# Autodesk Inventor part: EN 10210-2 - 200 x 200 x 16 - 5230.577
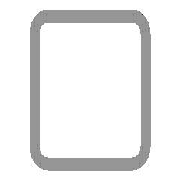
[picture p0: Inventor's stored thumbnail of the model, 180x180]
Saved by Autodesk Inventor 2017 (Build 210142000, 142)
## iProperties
IsCustomPart: 1
Created: 2016-02
Part Number: EN 10210-2 - 200 x 200 x 16 - 5230.577
Material: Steel, Mild
Description: Tube
Document SubType Name: Modeling
Standard: DIN
Designer: iusti
Standard Revision: 2006-07
Standards Organization: DIN
Language: en-US
Size Designation: 200 x 200 x 16
Categories: <MemberInstance><Categories><Category DisplayName="Structural Shapes" InternalName="089c4875-fa83-4c05-b084-43b9cc11f5ed" Mnemonic="GRDR"><CategoryParameter Dis
Stock Number: 200 x 200 x 16
Density: 7.85 g/cm^3
Appearance: Semi-Polished
Mass: 461295 g
Surface Area: 71973.4 cm^2
Volume: 58763.7 cm^3
_CCFamilyMember: 94
_CCFamilyDisplayName: DIN EN 10210-2 (Square) - Tube — Sizes in parentheses have been withdrawn
_FrameMemberDoc: Frame Member File
_Version: 15.0.0
_GetPNFromCC: 1
G_L: 5230.577 mm
G_W: 200.000 mm
G_H: 200.000 mm
+346FD258-9F9C-4BDE-884E-4FE9BE76FCEA+CUTDETAIL1: Miter 69.88 deg
+29768780-A419-4CF3-9340-1BC278E7B28F+CUTDETAIL2: Cut
Author: iusti
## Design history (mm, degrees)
node "Start plane"
node "End plane"
sketch "Sketch"
  geometry: L1 (-100, -76)-(-100, 76); L2 (-76, 100)-(76, 100); L3 (100, 76)-(100, -76); L4 (76, -100)-(-76, -100); L5 (-68, 84)-(68, 84); L6 (84, 68)-(84, -68); L7 (68, -84)-(-68, -84); L8 (-84, -68)-(-84, 68); L9 (0, 146.959)-(0, -146.959) reference; L10 (-146.959, 0)-(146.959, 0) reference; A1 r 24 centre (-76, -76) between (-100, -76) and (-76, -100); A2 r 24 centre (-76, 76) between (-76, 100) and (-100, 76); A3 r 24 centre (76, 76) between (100, 76) and (76, 100); A4 r 24 centre (76, -76) between (76, -100) and (100, -76); A5 r 16 centre (-68, -68) between (-84, -68) and (-68, -84); A6 r 16 centre (-68, 68) between (-68, 84) and (-84, 68); A7 r 16 centre (68, 68) between (84, 68) and (68, 84); A8 r 16 centre (68, -68) between (68, -84) and (84, -68)
  constraints: 16 end point, 16 point on circle, 16 tangent, 8 centre point, 6 equal radius, 4 parallel, 2 perpendicular, 2 other
  dimensions: "d7" = 24 radius of A1 (= G_IR); "d10" = 200 distance between parallel lines of L2 L4 (= G_H); "d11" = 200 distance between parallel lines of L1 L3 (= G_W); "d12" = 16 distance between parallel lines of L3 L6 (= G_T); "d15" = 100 distance between parallel lines of L2 L10 (= 0.5 x d10); "d16" = 100 distance between parallel lines of L9 L3 (= 0.5 x d11); "d19" = 16 radius of A5 (= G_T); "d20" = 16 distance between parallel lines of L4 L7 (= G_T)
extrude "Body" new body sketch "Sketch" stored distance "d3" = 5230.57682 (= G_L); taper "d4" = 0 deg
node "Driven Length"
  sketch "Sketch3"
    geometry: L1 (0, 0)-(10, 0) reference
    constraints: 2 end point, 1 horizontal
  workplane "Work Plane3"
  sketch "Sketch4"
    geometry: L1 (-2, 46.373)-(12, 46.373) reference; L2 (-2, 5276.95)-(12, 5276.95) reference
    dimensions: "d18" = 5230.57682 distance between parallel lines of L1 L2 (derived)
workplane "Work Plane4"
split "Split1"
workplane "Work Plane5"
split "Split2"
body "Solid1"
other parameters: "G_W" = 200 [user parameter; used in 1 equation term], "G_H" = 200 [user parameter; used in 1 equation term], "G_T" = 16 [user parameter; used in 3 equation terms], "G_IR" = 24 [user parameter; used in 1 equation term], "G_L" = 5230.57682 (= d18) [user parameter; used in 1 equation term], "G_OFFSET_START" = -46.37302 [user parameter; used in 1 equation term], "G_OFFSET_END" = 36.6372 [user parameter; used in 1 equation term], "d13" = 46.37302 (= -G_OFFSET_START), "d14" = 5276.94984 (= G_OFFSET_END + B_L), "B_L" = 5240.31264 [user parameter; used in 1 equation term], "d17" = 90 deg
